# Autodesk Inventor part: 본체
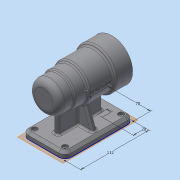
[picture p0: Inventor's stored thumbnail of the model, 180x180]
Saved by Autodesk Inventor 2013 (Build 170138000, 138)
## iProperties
Created: 2016-06
Part Number: 본체
Material: 일반
Document SubType Name: Modeling
Designer: dgall
Density: 1 g/cm^3
Author: dgall
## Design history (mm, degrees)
sketch "스케치1"
  geometry: L1 (-56, 0)-(56, 0); L2 (-56, 0)-(-56, 25); L3 (-56, 25)-(-31, 25); L4 (-31, 25)-(-31, 27); L5 (-31, 27)-(-11, 27); L6 (-11, 27)-(-11, 30); L7 (-11, 30)-(28, 30); L8 (28, 30)-(28, 34); L9 (28, 34)-(56, 34); L10 (56, 34)-(56, 21); L11 (56, 21)-(41, 21); L12 (41, 21)-(41, 21); L13 (38, 24)-(-10, 24); L14 (-13, 21)-(-13, 21); L15 (-13, 21)-(-24.7, 21); L16 (-25, 20.7)-(-25, 17.5); L17 (-25, 17.5)-(-42.7, 17.5); L18 (-43, 17.2)-(-43, 16); L19 (-43, 16)-(-46.7, 16); L20 (-47, 15.7)-(-47, 10.5); L21 (-47, 10.5)-(-47, 10.5); L22 (-50, 7.5)-(-50, 0); A1 r 3 centre (-10, 21) between (-10, 24) and (-13, 21); A2 r 3 centre (38, 21) between (41, 21) and (38, 24); A3 r 3 centre (-47, 7.5) between (-47, 10.5) and (-50, 7.5); A4 r 0.3 centre (-46.7, 15.7) between (-46.7, 16) and (-47, 15.7); A5 r 0.3 centre (-42.7, 17.2) between (-42.7, 17.5) and (-43, 17.2); A6 r 0.3 centre (-24.7, 20.7) between (-24.7, 21) and (-25, 20.7); 8 further points
  constraints: 44 end point, 15 parallel, 13 point on line, 12 point on circle, 12 tangent, 6 centre point, 5 perpendicular, 4 equal radius, 1 coincident, 1 collinear, 1 horizontal, 1 midpoint, 1 vertical alignment
  dimensions: "d0" = 112 distance of L1.start L1.end; "d2" = 50 diameter of L3 L1; "d3" = 54 diameter of L5 L1; "d4" = 60 diameter of L7 L1; "d5" = 68 diameter of L9 L1; "d6" = 25 distance of L2.end L3.end; "d7" = 45 distance between parallel lines of L6 L2; "d8" = 84 distance between parallel lines of L2 L8; "d9" = 21 diameter of L21 L1; "d10" = 15 distance of L10.end L11.end; "d11" = 42 diameter of L11 L1; "d13" = 48 diameter of L13 L1; "d14" = 54 distance of point (41, 24) point (-13, 24); "d15" = 12 distance of L14.end point (-25, 21); "d16" = 18 distance of L16.end point (-43, 17.5); "d17" = 4 distance of L18.end point (-47, 16); "d18" = 3 distance of L20.end point (-50, 10.5); "d19" = 32 diameter of L19 L1; "d20" = 35 diameter of L17 L1; "d21" = 42 diameter of L15 L1; "d25" = 3 radius of A1; "d26" = 0.3 radius of A4
revolve "회전1" sketch "스케치1" stored, may be unused: angle "d22" = 90 deg
fillet "모깎기1" dims "d23" = 10, "d24" = 3
node "작업 평면1"
sketch "스케치2"
  geometry: L1 (-25, 56)-(25, 56); L2 (35, 46)-(35, -46); L3 (25, -56)-(-25, -56); L4 (-35, -46)-(-35, 46); L5 (-4, 36)-(4, 36); L6 (4, 36)-(4, -36); L7 (4, -36)-(-4, -36); L8 (-4, -36)-(-4, 36); A1 r 10 centre (-25, 46) between (-25, 56) and (-35, 46); A2 r 10 centre (-25, -46) between (-35, -46) and (-25, -56); A3 r 10 centre (25, -46) between (25, -56) and (35, -46); A4 r 10 centre (25, 46) between (35, 46) and (25, 56); 8 further points
  constraints: 16 end point, 8 point on circle, 8 tangent, 6 point on line, 4 centre point, 4 midpoint, 4 parallel, 3 equal radius, 2 horizontal, 2 horizontal alignment, 2 perpendicular, 2 vertical alignment
  dimensions: "d28" = 112 distance of point (35, 56) point (35, -56); "d30" = 70 distance of point (-35, 56) point (35, 56); "d31" = 10 radius of A1; "d32" = 8 distance of L5.start L5.end; "d33" = 20 distance from line of point (0, 36) L1
extrude "돌출1" join sketch "스케치2" distance "d34" = 10; taper "d35" = 0 deg
extrude "돌출2" join sketch "스케치2" stored distance "d36" = 10; taper "d37" = 0 deg
sketch "스케치3"
  geometry: L1 (-25, -60)-(25, -60) reference; L2 (-25, -60)-(-35, -60) reference; L3 (-28, -60)-(-15.509, -25.68); L4 (-35, -70)-(-35, -60) reference; A1 r 30 centre (0, 0) between (4, -29.732) and (-4, -29.732) reference; 1 further point
  constraints: 2 end point, 1 point on circle, 1 point on line
  dimensions: "d38" = 7 distance from line of L4 L3.start; "d39" = 110 deg angle of L3 L2
feature "리브1" sketch "스케치3" dims "d40" = 1, "d41" = 8, "d42" = 0, "d43" = 0, "d44" = 1, "d45" = 1
sketch "스케치4"
  geometry: C1 r 21 at (0, 0) reference; 1 further point
  constraints: 1 vertical alignment
  dimensions: "d46" = 26 distance of C1.centre point (0, -26)
hole "구멍1" sketch "스케치4" at (0, -26) diameter "d47" = 3.242; stored, may be unused: countersink angle "d51" = 90 deg, drill point angle "d53" = 118 deg; dims "d48" = 8, "d49" = 4, "d50" = 2, "d52" = 11
chamfer "모따기1" distance "d57" = 4; stored, may be unused: second distance "d58" = 2, angle "d59" = 45 deg
hole "구멍2" diameter "d62" = 5; stored, may be unused: countersink angle "d66" = 90 deg, drill point angle "d68" = 118 deg; dims "d60" = 10, "d61" = 10, "d63" = 8, "d64" = 9, "d65" = 4, "d67" = 11
fillet "모깎기2" dims "d69" = 3
fillet "모깎기3" dims "d70" = 3
node "작업 평면2"
sketch "스케치5"
  geometry: L1 (47.5, -34)-(47.5, 34) reference; 2 further points
  constraints: 1 horizontal alignment, 1 other
  dimensions: "d71" = 48 distance from line of L1 point (-0.5, 0)
feature "엠보싱1" sketch "스케치5" dims "d18" = 3, "d72" = 0.5, "d73" = 0
chamfer "모따기2" distance "d74" = 1; stored, may be unused: second distance "d75" = 2, angle "d76" = 45 deg
node "솔리드1"
mirror "대칭1"
pattern_circular "원형 패턴1" dims angle "d55" = 360 deg
mirror "대칭2"
mirror "대칭3"
